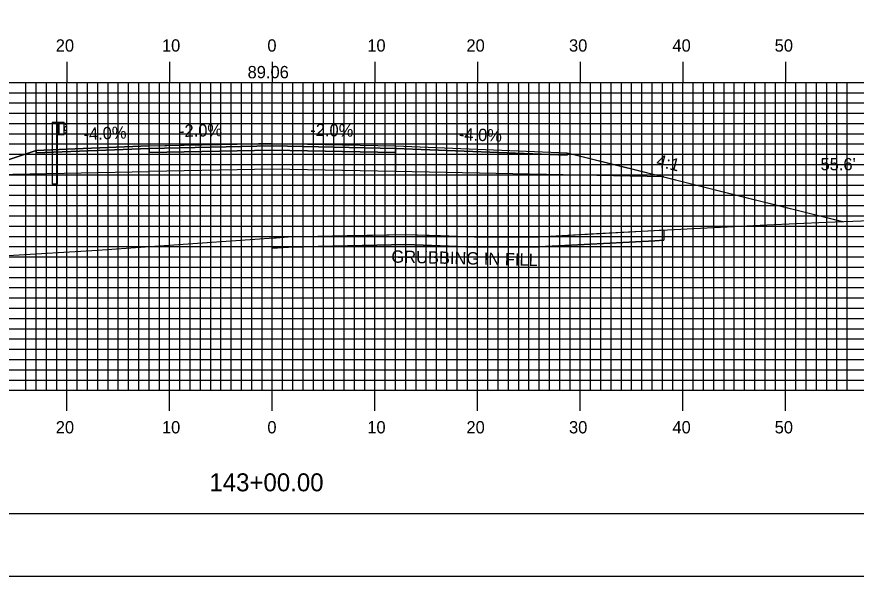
# Model space of a CAD drawing. Extents: x 1777138 to 1777481, y 442591 to 442811.
# Drawn here: x 1777278.9 to 1777360.6, y 442590.5 to 442645.1 of the extents above; entities that cross this region are included whole.
import ezdxf

# ---------------------------------------------------------------- set-up
doc = ezdxf.new("R2010")
doc.units = 0
for name, color, linetype in [('ANNOTATION', 7, 'Continuous'), ('BORDER', 7, 'Continuous'), ('D_Guardrail_Beam_Lt', 7, 'Continuous'), ('D_Roadway_Centerline', 7, 'Continuous'), ('D_Roadway_Centerline_Text', 7, 'Continuous'), ('D_Roadway_Edge_Shoulder', 7, 'Continuous'), ('D_Roadway_Edge_TW', 7, 'Continuous'), ('D_Roadway_Pavement', 7, 'Continuous'), ('D_Roadway_SlopeLines', 7, 'Continuous'), ('D_Roadway_SubGrade', 7, 'Continuous'), ('D_Text_Standard', 7, 'Continuous'), ('GRUBBING IN FILL', 7, 'Continuous'), ('H_V ANNOTATION', 7, 'Continuous'), ('MAJOR', 7, 'Continuous'), ('MINOR', 7, 'Continuous'), ('PLOT BOUNDARY', 7, 'Continuous'), ('S_Roadway_Centerline', 7, 'Continuous')]:
    doc.layers.add(name, color=color, linetype=linetype)

msp = doc.modelspace()

# ---------------------------------------------------------------- linework, layer by layer
at = {"layer": 'BORDER'}
msp.add_lwpolyline([(1777154.164, 442596.665), (1777474.164, 442596.665), (1777474.164, 442806.665), (1777154.164, 442806.665)], close=True, dxfattribs=at)
at = {"layer": 'D_Guardrail_Beam_Lt'}
for p, q in [((1777282.334, 442634.75), (1777282.334, 442628.75)), ((1777282.805, 442634.75), (1777282.334, 442634.75)), ((1777283.493, 442634.75), (1777282.805, 442634.75)), ((1777282.805, 442634.75), (1777282.805, 442633.583)), ((1777282.868, 442634.75), (1777282.868, 442633.583)), ((1777282.972, 442634.75), (1777282.972, 442633.583)), ((1777283.493, 442633.583), (1777283.493, 442634.75)), ((1777283.493, 442634.666), (1777283.567, 442634.652)), ((1777283.726, 442634.402), (1777283.531, 442634.266)), ((1777283.583, 442634.645), (1777283.726, 442634.545)), ((1777282.805, 442633.583), (1777283.493, 442633.583)), ((1777282.826, 442628.75), (1777282.826, 442633.583)), ((1777283.567, 442633.681), (1777283.493, 442633.666)), ((1777283.497, 442634.201), (1777283.497, 442634.131)), ((1777283.531, 442634.067), (1777283.726, 442633.931)), ((1777283.726, 442633.787), (1777283.583, 442633.687)), ((1777282.826, 442628.75), (1777282.334, 442628.75))]:
    msp.add_line(p, q, dxfattribs=at)
for centre, major_axis, start_param, end_param in [((1777283.576, 442634.201), (-0.0789, 0), 5.323254, 6.283185), ((1777283.559, 442634.611), (0.0417, 0), 0.959931, 1.376053), ((1777283.676, 442634.473), (0.0877, 0), 5.323254, 7.243116), ((1777283.576, 442634.131), (-0.0789, 0), 6.283185, 7.243116), ((1777283.559, 442633.721), (0.0417, 0), 4.907132, 5.323254), ((1777283.676, 442633.859), (0.0877, 0), 5.323254, 7.243116)]:
    msp.add_ellipse(centre, major_axis=major_axis, ratio=0.995501, start_param=start_param, end_param=end_param, dxfattribs=at)
at = {"layer": 'D_Roadway_Centerline'}
msp.add_lwpolyline([(1777245.694, 442620.356), (1777245.702, 442620.359), (1777255.627, 442623.667), (1777273.479, 442629.618), (1777273.487, 442629.621), (1777273.489, 442629.622), (1777275.77, 442630.382), (1777280.756, 442632.044), (1777280.764, 442632.046), (1777283.762, 442632.166), (1777283.764, 442632.166), (1777291.759, 442632.486), (1777291.764, 442632.486), (1777302.406, 442632.699), (1777303.763, 442632.726), (1777315.764, 442632.486), (1777315.772, 442632.486), (1777332.479, 442631.818), (1777338.695, 442630.264), (1777341.894, 442629.464), (1777344.477, 442628.819), (1777344.479, 442628.818), (1777349.238, 442627.628), (1777359.317, 442625.108)], dxfattribs=at)
at = {"layer": 'D_Roadway_Edge_Shoulder'}
for points in [[(1777291.764, 442632.486), (1777283.764, 442632.166), (1777283.764, 442632.166), (1777280.764, 442632.046), (1777280.764, 442631.796), (1777291.764, 442632.236)], [(1777315.764, 442632.486), (1777332.479, 442631.818), (1777332.479, 442631.568), (1777315.764, 442632.236)]]:
    msp.add_lwpolyline(points, close=True, dxfattribs=at)
at = {"layer": 'D_Roadway_Edge_TW'}
msp.add_lwpolyline([(1777291.764, 442632.236), (1777291.764, 442632.486), (1777303.763, 442632.726), (1777315.764, 442632.486), (1777315.764, 442632.236), (1777303.763, 442632.476)], close=True, dxfattribs=at)
at = {"layer": 'D_Roadway_Pavement'}
msp.add_lwpolyline([(1777291.764, 442631.82), (1777291.764, 442632.236), (1777303.763, 442632.476), (1777315.764, 442632.236), (1777315.764, 442631.82), (1777303.763, 442632.06)], close=True, dxfattribs=at)
for points in [[(1777291.764, 442632.236), (1777291.764, 442631.82)], [(1777315.764, 442632.236), (1777315.764, 442631.82)]]:
    msp.add_lwpolyline(points, dxfattribs=at)
at = {"layer": 'D_Roadway_SlopeLines'}
for points in [[(1777280.764, 442632.046), (1777245.694, 442620.356)], [(1777332.479, 442631.818), (1777344.479, 442628.818), (1777359.316, 442625.108)]]:
    msp.add_lwpolyline(points, dxfattribs=at)
at = {"layer": 'D_Roadway_SubGrade'}
for points in [[(1777291.764, 442631.82), (1777291.764, 442632.236), (1777280.764, 442631.796), (1777280.764, 442632.046), (1777273.487, 442629.621), (1777291.764, 442629.986)], [(1777291.764, 442629.986), (1777291.764, 442632.236), (1777291.764, 442631.82), (1777303.763, 442632.06), (1777315.764, 442631.82), (1777315.764, 442632.236), (1777315.764, 442629.986), (1777303.763, 442630.226)], [(1777315.764, 442631.82), (1777315.764, 442632.236), (1777332.479, 442631.568), (1777332.479, 442631.818), (1777341.894, 442629.464), (1777315.764, 442629.986)]]:
    msp.add_lwpolyline(points, close=True, dxfattribs=at)
at = {"layer": 'GRUBBING IN FILL'}
msp.add_line((1777341.894, 442624.288), (1777341.894, 442623.287), dxfattribs=at)
msp.add_line((1777341.894, 442624.288), (1777341.894, 442623.287), dxfattribs=at)
msp.add_lwpolyline([(1777341.894, 442624.288), (1777341.894, 442623.287), (1777341.02, 442623.244), (1777335.392, 442622.938), (1777329.764, 442622.633), (1777326.602, 442622.624), (1777323.439, 442622.615), (1777316.798, 442622.858), (1777311.074, 442622.735), (1777305.35, 442622.611), (1777303.764, 442622.5), (1777303.764, 442623.503), (1777305.304, 442623.611), (1777311.055, 442623.735), (1777316.806, 442623.859), (1777320.131, 442623.737), (1777323.456, 442623.615), (1777326.596, 442623.624), (1777329.736, 442623.633), (1777335.352, 442623.938), (1777340.969, 442624.243)], close=True, dxfattribs=at)
msp.add_lwpolyline([(1777341.894, 442624.288), (1777341.894, 442623.287), (1777341.02, 442623.244), (1777335.392, 442622.938), (1777329.764, 442622.633), (1777326.602, 442622.624), (1777323.439, 442622.615), (1777316.798, 442622.858), (1777311.074, 442622.735), (1777305.35, 442622.611), (1777303.764, 442622.5), (1777303.764, 442623.503), (1777305.304, 442623.611), (1777311.055, 442623.735), (1777316.806, 442623.859), (1777320.131, 442623.737), (1777323.456, 442623.615), (1777326.596, 442623.624), (1777329.736, 442623.633), (1777335.352, 442623.938), (1777340.969, 442624.243)], close=True, dxfattribs=at)
msp.add_lwpolyline([(1777303.764, 442622.5), (1777305.35, 442622.611), (1777316.798, 442622.858), (1777323.439, 442622.615), (1777329.764, 442622.633), (1777341.02, 442623.244), (1777341.894, 442623.287)], dxfattribs=at)
msp.add_lwpolyline([(1777303.764, 442622.5), (1777305.35, 442622.611), (1777316.798, 442622.858), (1777323.439, 442622.615), (1777329.764, 442622.633), (1777341.02, 442623.244), (1777341.894, 442623.287)], dxfattribs=at)
at = {"layer": 'MAJOR'}
for p, q in [((1777283.764, 442640.669), (1777283.764, 442638.665)), ((1777293.764, 442640.669), (1777293.764, 442638.665)), ((1777303.764, 442640.669), (1777303.764, 442638.665)), ((1777313.764, 442640.669), (1777313.764, 442638.665)), ((1777323.764, 442640.669), (1777323.764, 442638.665)), ((1777333.764, 442640.669), (1777333.764, 442638.665)), ((1777343.764, 442640.669), (1777343.764, 442638.665)), ((1777353.764, 442640.669), (1777353.764, 442638.665)), ((1777163.764, 442638.665), (1777443.764, 442638.665)), ((1777163.764, 442638.665), (1777443.764, 442638.665)), ((1777283.764, 442608.665), (1777283.764, 442638.665)), ((1777293.764, 442608.665), (1777293.764, 442638.665)), ((1777303.764, 442608.665), (1777303.764, 442638.665)), ((1777313.764, 442608.665), (1777313.764, 442638.665)), ((1777323.764, 442608.665), (1777323.764, 442638.665)), ((1777333.764, 442608.665), (1777333.764, 442638.665)), ((1777343.764, 442608.665), (1777343.764, 442638.665)), ((1777353.764, 442608.665), (1777353.764, 442638.665)), ((1777163.764, 442633.665), (1777443.764, 442633.665)), ((1777163.764, 442628.665), (1777443.764, 442628.665)), ((1777163.764, 442623.665), (1777443.764, 442623.665)), ((1777163.764, 442618.665), (1777443.764, 442618.665)), ((1777163.764, 442613.665), (1777443.764, 442613.665)), ((1777163.764, 442608.665), (1777443.764, 442608.665)), ((1777163.764, 442608.665), (1777443.764, 442608.665)), ((1777283.764, 442606.661), (1777283.764, 442608.665)), ((1777293.764, 442606.661), (1777293.764, 442608.665)), ((1777303.764, 442606.661), (1777303.764, 442608.665)), ((1777313.764, 442606.661), (1777313.764, 442608.665)), ((1777323.764, 442606.661), (1777323.764, 442608.665)), ((1777333.764, 442606.661), (1777333.764, 442608.665)), ((1777343.764, 442606.661), (1777343.764, 442608.665)), ((1777353.764, 442606.661), (1777353.764, 442608.665))]:
    msp.add_line(p, q, dxfattribs=at)
at = {"layer": 'MINOR'}
for p, q in [((1777279.764, 442608.665), (1777279.764, 442638.665)), ((1777280.764, 442608.665), (1777280.764, 442638.665)), ((1777281.764, 442608.665), (1777281.764, 442638.665)), ((1777282.764, 442608.665), (1777282.764, 442638.665)), ((1777284.764, 442608.665), (1777284.764, 442638.665)), ((1777285.764, 442608.665), (1777285.764, 442638.665)), ((1777286.764, 442608.665), (1777286.764, 442638.665)), ((1777287.764, 442608.665), (1777287.764, 442638.665)), ((1777288.764, 442608.665), (1777288.764, 442638.665)), ((1777289.764, 442608.665), (1777289.764, 442638.665)), ((1777290.764, 442608.665), (1777290.764, 442638.665)), ((1777291.764, 442608.665), (1777291.764, 442638.665)), ((1777292.764, 442608.665), (1777292.764, 442638.665)), ((1777294.764, 442608.665), (1777294.764, 442638.665)), ((1777295.764, 442608.665), (1777295.764, 442638.665)), ((1777296.764, 442608.665), (1777296.764, 442638.665)), ((1777297.764, 442608.665), (1777297.764, 442638.665)), ((1777298.764, 442608.665), (1777298.764, 442638.665)), ((1777299.764, 442608.665), (1777299.764, 442638.665)), ((1777300.764, 442608.665), (1777300.764, 442638.665)), ((1777301.764, 442608.665), (1777301.764, 442638.665)), ((1777302.764, 442608.665), (1777302.764, 442638.665)), ((1777304.764, 442608.665), (1777304.764, 442638.665)), ((1777305.764, 442608.665), (1777305.764, 442638.665)), ((1777306.764, 442608.665), (1777306.764, 442638.665)), ((1777307.764, 442608.665), (1777307.764, 442638.665)), ((1777308.764, 442608.665), (1777308.764, 442638.665)), ((1777309.764, 442608.665), (1777309.764, 442638.665)), ((1777310.764, 442608.665), (1777310.764, 442638.665)), ((1777311.764, 442608.665), (1777311.764, 442638.665)), ((1777312.764, 442608.665), (1777312.764, 442638.665)), ((1777314.764, 442608.665), (1777314.764, 442638.665)), ((1777315.764, 442608.665), (1777315.764, 442638.665)), ((1777316.764, 442608.665), (1777316.764, 442638.665)), ((1777317.764, 442608.665), (1777317.764, 442638.665)), ((1777318.764, 442608.665), (1777318.764, 442638.665)), ((1777319.764, 442608.665), (1777319.764, 442638.665)), ((1777320.764, 442608.665), (1777320.764, 442638.665)), ((1777321.764, 442608.665), (1777321.764, 442638.665)), ((1777322.764, 442608.665), (1777322.764, 442638.665)), ((1777324.764, 442608.665), (1777324.764, 442638.665)), ((1777325.764, 442608.665), (1777325.764, 442638.665)), ((1777326.764, 442608.665), (1777326.764, 442638.665)), ((1777327.764, 442608.665), (1777327.764, 442638.665)), ((1777328.764, 442608.665), (1777328.764, 442638.665)), ((1777329.764, 442608.665), (1777329.764, 442638.665)), ((1777330.764, 442608.665), (1777330.764, 442638.665)), ((1777331.764, 442608.665), (1777331.764, 442638.665)), ((1777332.764, 442608.665), (1777332.764, 442638.665)), ((1777334.764, 442608.665), (1777334.764, 442638.665)), ((1777335.764, 442608.665), (1777335.764, 442638.665)), ((1777336.764, 442608.665), (1777336.764, 442638.665)), ((1777337.764, 442608.665), (1777337.764, 442638.665)), ((1777338.764, 442608.665), (1777338.764, 442638.665)), ((1777339.764, 442608.665), (1777339.764, 442638.665)), ((1777340.764, 442608.665), (1777340.764, 442638.665)), ((1777341.764, 442608.665), (1777341.764, 442638.665)), ((1777342.764, 442608.665), (1777342.764, 442638.665)), ((1777344.764, 442608.665), (1777344.764, 442638.665)), ((1777345.764, 442608.665), (1777345.764, 442638.665)), ((1777346.764, 442608.665), (1777346.764, 442638.665)), ((1777347.764, 442608.665), (1777347.764, 442638.665)), ((1777348.764, 442608.665), (1777348.764, 442638.665)), ((1777349.764, 442608.665), (1777349.764, 442638.665)), ((1777350.764, 442608.665), (1777350.764, 442638.665)), ((1777351.764, 442608.665), (1777351.764, 442638.665)), ((1777352.764, 442608.665), (1777352.764, 442638.665)), ((1777354.764, 442608.665), (1777354.764, 442638.665)), ((1777355.764, 442608.665), (1777355.764, 442638.665)), ((1777356.764, 442608.665), (1777356.764, 442638.665)), ((1777357.764, 442608.665), (1777357.764, 442638.665)), ((1777358.764, 442608.665), (1777358.764, 442638.665)), ((1777359.764, 442608.665), (1777359.764, 442638.665)), ((1777163.764, 442637.665), (1777443.764, 442637.665)), ((1777163.764, 442636.665), (1777443.764, 442636.665)), ((1777163.764, 442635.665), (1777443.764, 442635.665)), ((1777163.764, 442634.665), (1777443.764, 442634.665)), ((1777163.764, 442632.665), (1777443.764, 442632.665)), ((1777163.764, 442631.665), (1777443.764, 442631.665)), ((1777163.764, 442630.665), (1777443.764, 442630.665)), ((1777163.764, 442629.665), (1777443.764, 442629.665)), ((1777163.764, 442627.665), (1777443.764, 442627.665)), ((1777163.764, 442626.665), (1777443.764, 442626.665)), ((1777163.764, 442625.665), (1777443.764, 442625.665)), ((1777163.764, 442624.665), (1777443.764, 442624.665)), ((1777163.764, 442622.665), (1777443.764, 442622.665)), ((1777163.764, 442621.665), (1777443.764, 442621.665)), ((1777163.764, 442620.665), (1777443.764, 442620.665)), ((1777163.764, 442619.665), (1777443.764, 442619.665)), ((1777163.764, 442617.665), (1777443.764, 442617.665)), ((1777163.764, 442616.665), (1777443.764, 442616.665)), ((1777163.764, 442615.665), (1777443.764, 442615.665)), ((1777163.764, 442614.665), (1777443.764, 442614.665)), ((1777163.764, 442612.665), (1777443.764, 442612.665)), ((1777163.764, 442611.665), (1777443.764, 442611.665)), ((1777163.764, 442610.665), (1777443.764, 442610.665)), ((1777163.764, 442609.665), (1777443.764, 442609.665))]:
    msp.add_line(p, q, dxfattribs=at)
at = {"layer": 'PLOT BOUNDARY'}
msp.add_lwpolyline([(1777137.977, 442590.547), (1777477.977, 442590.547), (1777477.977, 442810.547), (1777137.977, 442810.547)], close=True, dxfattribs=at)
at = {"layer": 'S_Roadway_Centerline'}
msp.add_lwpolyline([(1777233.072, 442620.164), (1777249.826, 442620.42), (1777252.586, 442620.425), (1777256.648, 442620.624), (1777272.219, 442621.418), (1777276.276, 442621.72), (1777278.005, 442621.793), (1777286.74, 442622.312), (1777305.304, 442623.611), (1777316.806, 442623.859), (1777323.456, 442623.615), (1777329.736, 442623.633), (1777340.969, 442624.243), (1777351.939, 442624.78), (1777357.721, 442625.052), (1777363.737, 442625.264)], dxfattribs=at)

# ---------------------------------------------------------------- texts
at = {"layer": 'ANNOTATION'}
for s, rotation, p in [('-4.0%', 2.29054, (1777285.393, 442633.033)), ('-2.0%', 1.14582, (1777294.691, 442633.345)), ('-2.0%', 358.85431, (1777307.45, 442633.453)), ('-4.0%', 357.71144, (1777321.917, 442633.042)), ('4:1', 345.96466, (1777341.092, 442630.527))]:
    msp.add_text(s, height=1.2, rotation=rotation, dxfattribs=at).set_placement(p)
at = {"layer": 'D_Roadway_Centerline'}
for s, p in [('C', (1777303.758, 442632.726)), ('L', (1777303.763, 442632.719))]:
    msp.add_text(s, height=0.0146, dxfattribs=at).set_placement(p)
at = {"layer": 'D_Roadway_Centerline_Text'}
msp.add_text('89.06', height=1.2, dxfattribs=at).set_placement((1777301.356, 442639.068))
at = {"layer": 'D_Text_Standard'}
msp.add_text("55.6'", height=1.2, dxfattribs=at).set_placement((1777357.159, 442630.101))
at = {"layer": 'GRUBBING IN FILL'}
msp.add_text('GRUBBING IN FILL', height=1.2, rotation=358.64576, dxfattribs=at).set_placement((1777315.347, 442621.109))
at = {"layer": 'H_V ANNOTATION'}
for s, height, p in [('20', 1.2, (1777282.672, 442641.665)), ('10', 1.2, (1777293.014, 442641.665)), ('0', 1.2, (1777303.282, 442641.665)), ('10', 1.2, (1777313.014, 442641.665)), ('20', 1.2, (1777322.672, 442641.665)), ('30', 1.2, (1777332.661, 442641.665)), ('40', 1.2, (1777342.736, 442641.665)), ('50', 1.2, (1777352.693, 442641.665)), ('20', 1.2, (1777282.672, 442604.465)), ('10', 1.2, (1777293.014, 442604.465)), ('0', 1.2, (1777303.282, 442604.465)), ('10', 1.2, (1777313.014, 442604.465)), ('20', 1.2, (1777322.672, 442604.465)), ('30', 1.2, (1777332.661, 442604.465)), ('40', 1.2, (1777342.736, 442604.465)), ('50', 1.2, (1777352.693, 442604.465)), ('143+00.00', 1.75, (1777297.631, 442598.821))]:
    msp.add_text(s, height=height, dxfattribs=at).set_placement(p)

doc.saveas('drawing.dxf')
